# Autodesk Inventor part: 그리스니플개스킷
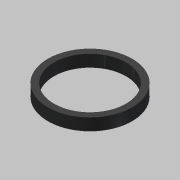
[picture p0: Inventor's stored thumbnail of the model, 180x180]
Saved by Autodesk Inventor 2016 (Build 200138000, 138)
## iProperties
Created: 2019-05
Part Number: 그리스니플개스킷
Material: 고무
Document SubType Name: Modeling
Designer: mduedu
Density: 1 g/cm^3
Appearance: 고무 - 검은색 - 버전 1.1
Author: mduedu
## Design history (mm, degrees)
sketch "스케치1"
  geometry: C1 r 3 at (0, 0); C2 r 3.5 at (0, 0); 1 further point
  constraints: 2 centre point, 2 coincident
  dimensions: "d0" = 6 diameter of C1; "d1" = 7 diameter of C2
extrude "돌출1" new body sketch "스케치1" distance "d2" = 1; taper "d3" = 0 deg
node "솔리드1"
